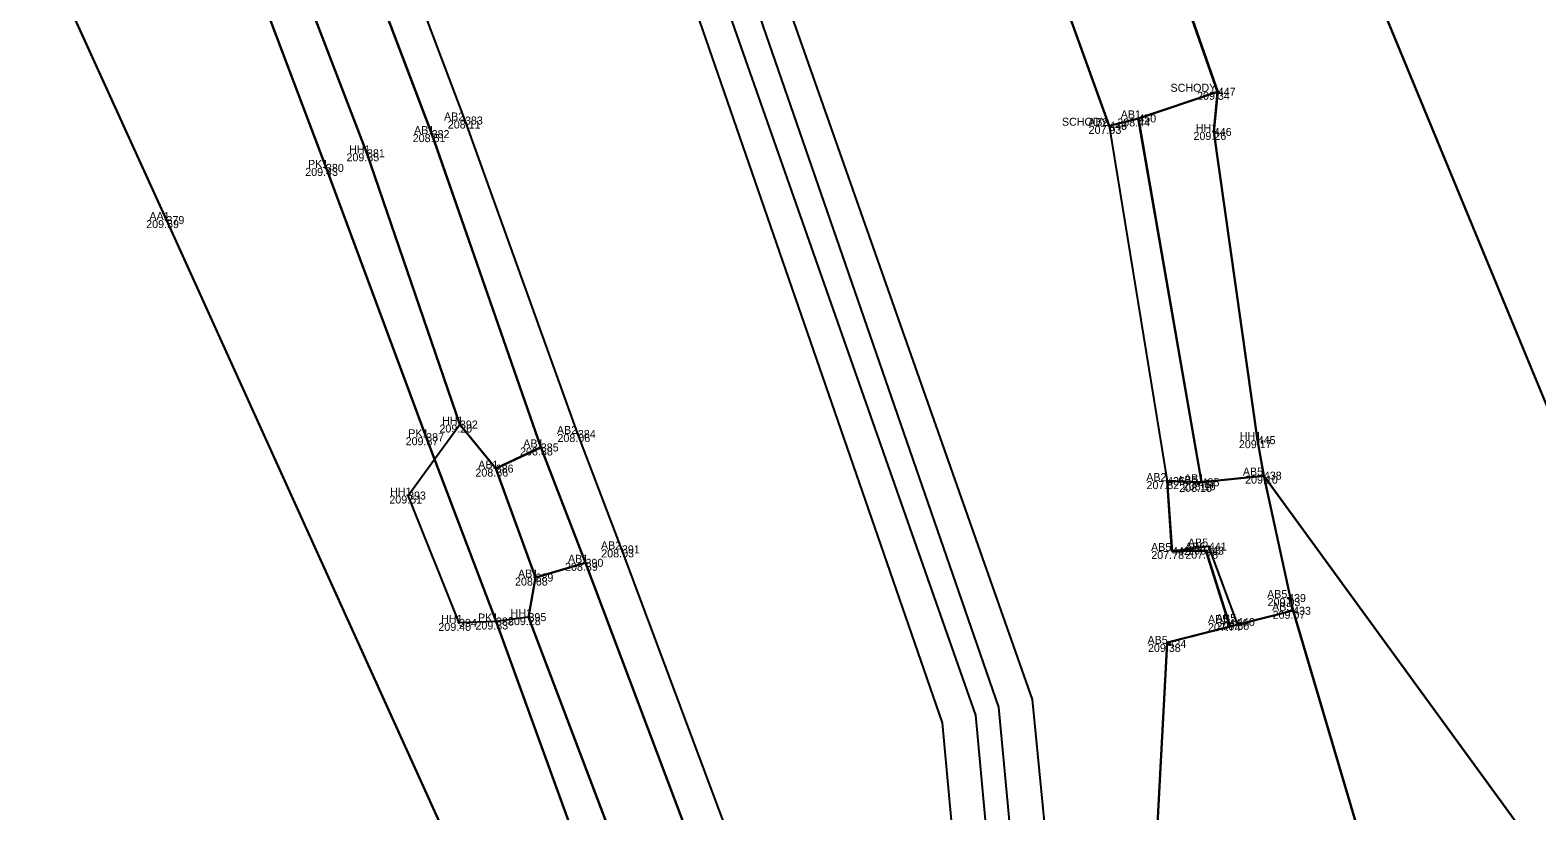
# Model space of a CAD drawing. Extents: x -263091 to -262565, y -1238731 to -1237092.
# Drawn here: x -262849.37 to -262811.71, y -1238683.21 to -1238663.71 of the extents above; entities that cross this region are included whole.
import ezdxf

# ---------------------------------------------------------------- set-up
doc = ezdxf.new("R2010")
doc.units = 0
for name, color, linetype in [('01_Hrana_betónu', 7, 'Continuous'), ('02_Oplotenie', 7, 'Continuous'), ('03_Asfalt', 7, 'Continuous'), ('05_Hrana_terénu', 7, 'Continuous'), ('06_Schody', 7, 'Continuous'), ('07_Iné', 7, 'Continuous'), ('08_Mimo_zelene', 7, 'Continuous'), ('Groma (21)', 7, 'Continuous'), ('Groma (22)', 7, 'Continuous'), ('Groma (23)', 7, 'Continuous'), ('Groma (24)', 7, 'Continuous'), ('U001_Betónové_panely_oblast', 7, 'Continuous'), ('U001_Betóny_prídavné', 7, 'Continuous'), ('U001_Ostatné_plochy', 7, 'Continuous'), ('U001_Schody', 7, 'Continuous'), ('U001_Zeleň_mimo', 7, 'Continuous'), ('U001_Zeleň_vnútro', 7, 'Continuous'), ('U001_Zeleň_zatrávňovač', 7, 'Continuous')]:
    doc.layers.add(name, color=color, linetype=linetype)

msp = doc.modelspace()

# ---------------------------------------------------------------- linework, layer by layer
at = {"layer": '01_Hrana_betónu'}
for p, q in [((-262822.4, -1238666.098), (-262820.949, -1238674.974)), ((-262820.09, -1238675.003), (-262821.671, -1238665.912))]:
    msp.add_line(p, q, dxfattribs=at)
for points in [[(-262945.09, -1238415.05), (-262943.108, -1238420.999), (-262942.065, -1238424.139), (-262934.754, -1238438.855), (-262923.683, -1238461.06), (-262913.753, -1238481.232), (-262903.896, -1238501.06), (-262894.759, -1238519.856), (-262890.317, -1238530.551), (-262883.158, -1238545.169), (-262873.572, -1238564.111), (-262869.728, -1238571.951), (-262860.562, -1238590.864), (-262854.835, -1238604.812), (-262840.38, -1238642.586), (-262833.174, -1238661.935), (-262826.575, -1238681.018), (-262825.738, -1238690.053), (-262824.527, -1238692.082)], [(-262821.464, -1238691.979), (-262823.978, -1238691.385), (-262824.893, -1238689.953), (-262825.729, -1238680.825), (-262832.468, -1238661.625), (-262839.672, -1238642.452), (-262854.271, -1238604.655), (-262859.863, -1238590.55), (-262868.949, -1238571.69), (-262872.864, -1238563.867), (-262882.403, -1238544.934), (-262889.591, -1238530.296), (-262894.035, -1238519.557), (-262903.102, -1238500.748), (-262912.912, -1238480.97), (-262922.987, -1238460.594), (-262933.962, -1238438.502), (-262941.314, -1238423.977), (-262942.296, -1238420.781), (-262943.962, -1238415.15)], [(-262941.142, -1238415.313), (-262941.461, -1238420.191), (-262940.383, -1238424.238), (-262933.343, -1238438.564), (-262922.27, -1238460.876), (-262912.449, -1238480.877), (-262902.557, -1238500.683), (-262893.416, -1238519.552), (-262889.058, -1238529.686), (-262881.962, -1238544.577), (-262872.106, -1238564.019), (-262868.478, -1238571.232), (-262859.211, -1238590.61), (-262852.998, -1238605.343), (-262846.933, -1238621.173), (-262838.559, -1238643.348), (-262831.894, -1238661.158), (-262825.164, -1238680.62), (-262824.312, -1238689.696), (-262823.847, -1238690.483), (-262822.763, -1238690.91), (-262821.486, -1238690.803)], [(-262821.555, -1238690.42), (-262822.731, -1238690.203), (-262823.426, -1238689.509), (-262824.318, -1238680.43), (-262831.163, -1238660.976), (-262837.946, -1238643.111), (-262846.365, -1238620.94), (-262852.333, -1238605.156), (-262858.618, -1238590.245), (-262867.784, -1238570.905), (-262871.416, -1238563.68), (-262881.223, -1238544.283), (-262888.392, -1238529.442), (-262892.626, -1238519.239), (-262901.725, -1238500.385), (-262911.6, -1238480.51), (-262921.479, -1238460.51), (-262932.607, -1238438.043), (-262939.752, -1238424.147), (-262940.771, -1238420.267), (-262940.559, -1238417.612), (-262940.205, -1238415.315)], [(-262821.612, -1238692.34), (-262824.527, -1238692.082), (-262827.229, -1238691.842), (-262828.578, -1238691.545), (-262829.254, -1238690.927), (-262834.577, -1238676.68), (-262835.677, -1238673.797), (-262838.498, -1238665.964), (-262846.729, -1238644.188), (-262854.634, -1238622.918), (-262863.262, -1238600.529), (-262868.088, -1238589.608)], [(-262868.934, -1238589.993), (-262864.101, -1238600.869), (-262855.602, -1238623.066), (-262847.622, -1238644.482), (-262839.332, -1238666.304), (-262836.604, -1238674.133), (-262835.486, -1238677.015), (-262830.144, -1238691.208), (-262829.282, -1238692.133), (-262827.58, -1238693.519), (-262820.969, -1238694.008)], [(-262820.949, -1238674.974), (-262820.828, -1238676.721), (-262819.978, -1238676.713), (-262819.376, -1238678.614), (-262820.948, -1238679.013), (-262821.555, -1238690.42)]]:
    msp.add_lwpolyline(points, dxfattribs=at)
at = {"layer": '02_Oplotenie'}
msp.add_lwpolyline([(-262896.033, -1238537.323), (-262884.611, -1238562.768), (-262875.332, -1238581.932), (-262871.26, -1238591.133), (-262867.507, -1238600.089), (-262859.113, -1238621.74), (-262850.323, -1238645.054), (-262841.974, -1238667.148), (-262839.469, -1238673.878), (-262839.26, -1238674.43), (-262837.725, -1238678.482), (-262834.801, -1238686.521), (-262833.14, -1238690.761), (-262828.35, -1238701.769), (-262822.156, -1238700.967), (-262816.462, -1238699.68), (-262807.77, -1238696.972), (-262807.339, -1238690.207)], dxfattribs=at)
at = {"layer": '03_Asfalt'}
for points in [[(-262804.465, -1238690.033), (-262818.631, -1238655.736), (-262826.695, -1238636.389), (-262836.855, -1238611.872), (-262842.406, -1238598.306), (-262850.452, -1238578.707), (-262858.82, -1238561.234), (-262870.509, -1238539), (-262873.344, -1238533.53), (-262876.375, -1238529.239), (-262880.031, -1238521.826), (-262869.115, -1238517.45), (-262870.175, -1238508.052), (-262871.319, -1238501.744), (-262886.895, -1238462.375), (-262895.067, -1238441.663), (-262905.824, -1238433.621), (-262917.716, -1238423.993), (-262928.896, -1238415.327), (-262941.774, -1238405.784), (-262954.673, -1238396.412), (-262962.054, -1238391.026)], [(-262881.2, -1238585.494), (-262874.644, -1238603.324), (-262866.886, -1238624.256), (-262857.388, -1238650.091), (-262854.721, -1238649.057), (-262851.25, -1238656.85), (-262845.959, -1238668.452), (-262837.314, -1238687.515), (-262834.926, -1238686.561), (-262833.211, -1238690.828), (-262828.426, -1238701.842), (-262822.233, -1238701.015), (-262822.159, -1238701.403), (-262816.354, -1238699.919), (-262807.207, -1238697.538)]]:
    msp.add_lwpolyline(points, dxfattribs=at)
at = {"layer": '05_Hrana_terénu'}
for points in [[(-262820.846, -1238694.953), (-262821.157, -1238695.132), (-262824.214, -1238695.234), (-262827.282, -1238694.67), (-262827.759, -1238694.543), (-262829.668, -1238693.915), (-262830.272, -1238693.55), (-262831.828, -1238691.771), (-262836.912, -1238678.373), (-262837.725, -1238678.482), (-262838.648, -1238678.516), (-262839.921, -1238675.334), (-262839.26, -1238674.43), (-262838.626, -1238673.561), (-262840.949, -1238666.783), (-262849.249, -1238645.167), (-262857.406, -1238624.309), (-262870.41, -1238590.811)], [(-262819.685, -1238665.246), (-262819.785, -1238666.25), (-262818.688, -1238673.951), (-262818.534, -1238674.837)]]:
    msp.add_lwpolyline(points, dxfattribs=at)
at = {"layer": '06_Schody'}
msp.add_lwpolyline([(-262825.01, -1238658.867), (-262824.362, -1238658.568), (-262822.278, -1238657.844), (-262819.685, -1238665.246), (-262821.671, -1238665.912), (-262822.4, -1238666.098)], close=True, dxfattribs=at)
at = {"layer": '07_Iné'}
for points in [[(-262835.486, -1238677.015), (-262836.736, -1238677.384), (-262837.731, -1238674.662), (-262836.604, -1238674.133)], [(-262820.828, -1238676.721), (-262820.949, -1238674.974), (-262820.09, -1238675.003), (-262818.534, -1238674.837), (-262817.803, -1238678.214), (-262819.181, -1238678.564), (-262819.908, -1238676.609), (-262820.828, -1238676.721), (-262819.978, -1238676.713), (-262819.376, -1238678.614)]]:
    msp.add_lwpolyline(points, dxfattribs=at)
at = {"layer": '08_Mimo_zelene'}
msp.add_lwpolyline([(-262817.803, -1238678.214), (-262819.181, -1238678.564), (-262819.376, -1238678.614), (-262820.948, -1238679.013), (-262821.555, -1238690.42), (-262821.486, -1238690.803), (-262821.464, -1238691.979), (-262821.612, -1238692.34), (-262819.863, -1238691.866), (-262819.273, -1238693.95), (-262818.147, -1238697.183), (-262812.645, -1238695.656), (-262813.715, -1238692.011)], close=True, dxfattribs=at)
at = {"layer": 'Groma (21)'}
for centre in [(-262819.685, -1238665.246), (-262838.498, -1238665.964), (-262822.4, -1238666.098), (-262822.399, -1238666.095), (-262821.671, -1238665.912), (-262839.332, -1238666.304), (-262819.785, -1238666.25), (-262840.949, -1238666.783), (-262841.974, -1238667.148), (-262845.959, -1238668.452), (-262838.626, -1238673.561), (-262839.469, -1238673.878), (-262835.677, -1238673.797), (-262818.688, -1238673.951), (-262836.604, -1238674.133), (-262837.731, -1238674.662), (-262818.534, -1238674.837), (-262820.949, -1238674.974), (-262820.175, -1238675.043), (-262820.09, -1238675.003), (-262839.921, -1238675.334), (-262834.577, -1238676.68), (-262820.828, -1238676.721), (-262819.978, -1238676.713), (-262819.908, -1238676.609), (-262835.486, -1238677.015), (-262836.736, -1238677.384), (-262817.928, -1238677.897), (-262817.803, -1238678.214), (-262838.648, -1238678.516), (-262837.725, -1238678.482), (-262836.912, -1238678.373), (-262819.406, -1238678.523), (-262819.206, -1238678.497), (-262820.917, -1238679.042)]:
    msp.add_circle(centre, 0.01, dxfattribs=at)
at = {"layer": 'U001_Betónové_panely_oblast'}
for points in [[(-262820.97, -1238694.01), (-262827.58, -1238693.52), (-262829.28, -1238692.13), (-262830.14, -1238691.21), (-262835.49, -1238677.02), (-262836.6, -1238674.13), (-262839.33, -1238666.3), (-262847.62, -1238644.48), (-262855.6, -1238623.07), (-262864.1, -1238600.87), (-262868.93, -1238589.99)], [(-262848.87, -1238596.84), (-262845.92, -1238603.87), (-262845.19, -1238603.53), (-262840.99, -1238614.59), (-262831.97, -1238638.45), (-262824.36, -1238658.57), (-262825.01, -1238658.87), (-262822.4, -1238666.1), (-262821.67, -1238665.91), (-262820.09, -1238675), (-262820.95, -1238674.97), (-262820.83, -1238676.72), (-262819.98, -1238676.71), (-262819.38, -1238678.61), (-262820.95, -1238679.01), (-262821.56, -1238690.42), (-262821.49, -1238690.8), (-262821.46, -1238691.98), (-262821.61, -1238692.34), (-262820.97, -1238694.01)], [(-262825.01, -1238658.87), (-262822.4, -1238666.1), (-262821.67, -1238665.91), (-262820.09, -1238675), (-262820.95, -1238674.97), (-262820.83, -1238676.72), (-262819.98, -1238676.71), (-262819.38, -1238678.61), (-262820.95, -1238679.01), (-262821.56, -1238690.42), (-262821.49, -1238690.8), (-262821.46, -1238691.98), (-262821.61, -1238692.34), (-262820.97, -1238694.01), (-262827.58, -1238693.52), (-262829.28, -1238692.13), (-262830.14, -1238691.21), (-262835.49, -1238677.02), (-262836.6, -1238674.13), (-262839.33, -1238666.3), (-262847.62, -1238644.48)]]:
    msp.add_lwpolyline(points, dxfattribs=at)
at = {"layer": 'U001_Betóny_prídavné'}
for points in [[(-262835.49, -1238677.02), (-262836.74, -1238677.38), (-262837.73, -1238674.66), (-262836.6, -1238674.13)], [(-262820.83, -1238676.72), (-262820.95, -1238674.97), (-262820.09, -1238675), (-262818.53, -1238674.84), (-262817.8, -1238678.21), (-262819.18, -1238678.56), (-262819.38, -1238678.61), (-262819.98, -1238676.71)]]:
    msp.add_lwpolyline(points, close=True, dxfattribs=at)
msp.add_lwpolyline([(-262819.38, -1238678.61), (-262819.98, -1238676.71), (-262820.83, -1238676.72), (-262820.95, -1238674.97), (-262820.09, -1238675), (-262818.53, -1238674.84), (-262817.8, -1238678.21), (-262819.18, -1238678.56), (-262819.38, -1238678.61)], dxfattribs=at)
at = {"layer": 'U001_Ostatné_plochy'}
msp.add_lwpolyline([(-262818.15, -1238697.18), (-262819.27, -1238693.95), (-262819.86, -1238691.87), (-262821.61, -1238692.34), (-262821.46, -1238691.98), (-262821.49, -1238690.8), (-262821.56, -1238690.42), (-262820.95, -1238679.01), (-262819.38, -1238678.61), (-262819.18, -1238678.56), (-262817.8, -1238678.21), (-262813.72, -1238692.01), (-262812.65, -1238695.66)], close=True, dxfattribs=at)
msp.add_lwpolyline([(-262818.15, -1238697.18), (-262819.27, -1238693.95), (-262819.86, -1238691.87), (-262821.61, -1238692.34), (-262821.46, -1238691.98), (-262821.49, -1238690.8), (-262821.56, -1238690.42), (-262820.95, -1238679.01), (-262819.38, -1238678.61), (-262819.18, -1238678.56), (-262817.8, -1238678.21), (-262813.72, -1238692.01), (-262812.65, -1238695.66), (-262818.15, -1238697.18)], dxfattribs=at)
at = {"layer": 'U001_Schody'}
msp.add_lwpolyline([(-262824.36, -1238658.57), (-262822.28, -1238657.84), (-262819.69, -1238665.25), (-262821.67, -1238665.91), (-262822.4, -1238666.1), (-262825.01, -1238658.87)], close=True, dxfattribs=at)
msp.add_lwpolyline([(-262822.4, -1238666.1), (-262825.01, -1238658.87), (-262824.36, -1238658.57), (-262822.28, -1238657.84), (-262819.69, -1238665.25), (-262821.67, -1238665.91), (-262822.4, -1238666.1)], dxfattribs=at)
at = {"layer": 'U001_Zeleň_mimo'}
for points in [[(-262962.05, -1238391.03), (-262954.67, -1238396.41), (-262941.77, -1238405.78), (-262928.9, -1238415.33), (-262917.72, -1238423.99), (-262905.82, -1238433.62), (-262895.07, -1238441.66), (-262886.9, -1238462.38), (-262871.32, -1238501.74), (-262870.18, -1238508.05), (-262869.12, -1238517.45), (-262880.03, -1238521.83), (-262876.38, -1238529.24), (-262873.34, -1238533.53), (-262870.51, -1238539), (-262858.82, -1238561.23), (-262850.45, -1238578.71), (-262842.41, -1238598.31), (-262836.86, -1238611.87), (-262826.7, -1238636.39), (-262818.63, -1238655.74), (-262804.47, -1238690.03)], [(-262807.21, -1238697.54), (-262816.35, -1238699.92), (-262822.16, -1238701.4), (-262822.23, -1238701.02), (-262828.43, -1238701.84), (-262833.21, -1238690.83), (-262834.93, -1238686.56), (-262837.31, -1238687.52), (-262845.96, -1238668.45), (-262851.25, -1238656.85), (-262854.72, -1238649.06), (-262857.39, -1238650.09), (-262866.89, -1238624.26), (-262874.64, -1238603.32), (-262881.2, -1238585.49)], [(-262871.26, -1238591.13), (-262867.51, -1238600.09), (-262859.11, -1238621.74), (-262850.32, -1238645.05), (-262841.97, -1238667.15), (-262839.47, -1238673.88), (-262839.26, -1238674.43), (-262837.72, -1238678.48), (-262834.8, -1238686.52), (-262833.14, -1238690.76), (-262828.35, -1238701.77), (-262822.16, -1238700.97), (-262816.46, -1238699.68), (-262807.77, -1238696.97)], [(-262807.34, -1238690.21), (-262818.53, -1238674.84), (-262818.69, -1238673.95), (-262819.78, -1238666.25), (-262819.69, -1238665.25), (-262822.28, -1238657.84), (-262830.39, -1238637.77), (-262839.6, -1238613.33), (-262842.24, -1238606.86), (-262843.24, -1238602.62), (-262846.18, -1238595.66)]]:
    msp.add_lwpolyline(points, dxfattribs=at)
at = {"layer": 'U001_Zeleň_vnútro'}
for points in [[(-262870.41, -1238590.81), (-262857.41, -1238624.31), (-262849.25, -1238645.17), (-262840.95, -1238666.78), (-262838.63, -1238673.56), (-262837.73, -1238674.66), (-262836.74, -1238677.38), (-262836.91, -1238678.37), (-262831.83, -1238691.77), (-262830.27, -1238693.55), (-262829.67, -1238693.92), (-262827.76, -1238694.54), (-262827.28, -1238694.67), (-262824.21, -1238695.23), (-262821.16, -1238695.13), (-262820.85, -1238694.95), (-262819.27, -1238693.95), (-262818.15, -1238697.18), (-262812.65, -1238695.66), (-262813.72, -1238692.01), (-262817.8, -1238678.21), (-262818.53, -1238674.84), (-262807.34, -1238690.21)], [(-262870.41, -1238590.81), (-262857.41, -1238624.31), (-262849.25, -1238645.17), (-262840.95, -1238666.78), (-262838.63, -1238673.56), (-262837.73, -1238674.66), (-262836.74, -1238677.38), (-262836.91, -1238678.37), (-262831.83, -1238691.77), (-262830.27, -1238693.55), (-262829.67, -1238693.92), (-262827.76, -1238694.54), (-262827.28, -1238694.67), (-262824.21, -1238695.23), (-262821.16, -1238695.13), (-262820.85, -1238694.95), (-262819.27, -1238693.95), (-262818.15, -1238697.18), (-262812.65, -1238695.66), (-262813.72, -1238692.01), (-262817.8, -1238678.21), (-262818.53, -1238674.84), (-262807.34, -1238690.21)], [(-262807.77, -1238696.97), (-262816.46, -1238699.68), (-262822.16, -1238700.97), (-262828.35, -1238701.77), (-262833.14, -1238690.76), (-262834.8, -1238686.52), (-262837.72, -1238678.48), (-262839.26, -1238674.43), (-262839.47, -1238673.88), (-262841.97, -1238667.15), (-262850.32, -1238645.05), (-262859.11, -1238621.74), (-262867.51, -1238600.09), (-262871.26, -1238591.13)], [(-262828.35, -1238701.77), (-262833.14, -1238690.76), (-262834.8, -1238686.52), (-262837.72, -1238678.48), (-262839.26, -1238674.43), (-262839.47, -1238673.88), (-262841.97, -1238667.15), (-262850.32, -1238645.05), (-262859.11, -1238621.74), (-262867.51, -1238600.09), (-262871.26, -1238591.13)]]:
    msp.add_lwpolyline(points, dxfattribs=at)
at = {"layer": 'U001_Zeleň_zatrávňovač'}
for points in [[(-262868.93, -1238589.99), (-262864.1, -1238600.87), (-262855.6, -1238623.07), (-262847.62, -1238644.48), (-262839.33, -1238666.3), (-262836.6, -1238674.13), (-262837.73, -1238674.66), (-262838.63, -1238673.56), (-262840.95, -1238666.78), (-262849.25, -1238645.17), (-262857.41, -1238624.31), (-262870.41, -1238590.81)], [(-262868.93, -1238589.99), (-262864.1, -1238600.87), (-262855.6, -1238623.07), (-262847.62, -1238644.48), (-262839.33, -1238666.3), (-262836.6, -1238674.13), (-262837.73, -1238674.66)], [(-262837.73, -1238674.66), (-262838.63, -1238673.56), (-262840.95, -1238666.78), (-262849.25, -1238645.17), (-262857.41, -1238624.31), (-262870.41, -1238590.81)], [(-262820.09, -1238675), (-262821.67, -1238665.91), (-262819.69, -1238665.25), (-262819.78, -1238666.25), (-262818.69, -1238673.95), (-262818.53, -1238674.84), (-262820.09, -1238675)], [(-262824.21, -1238695.23), (-262827.28, -1238694.67), (-262827.76, -1238694.54), (-262829.67, -1238693.92), (-262830.27, -1238693.55), (-262831.83, -1238691.77), (-262836.91, -1238678.37), (-262836.74, -1238677.38), (-262835.49, -1238677.02), (-262830.14, -1238691.21), (-262829.28, -1238692.13), (-262827.58, -1238693.52), (-262820.97, -1238694.01), (-262820.85, -1238694.95), (-262821.16, -1238695.13), (-262824.21, -1238695.23)]]:
    msp.add_lwpolyline(points, dxfattribs=at)
for points in [[(-262819.78, -1238666.25), (-262818.69, -1238673.95), (-262818.53, -1238674.84), (-262820.09, -1238675), (-262821.67, -1238665.91), (-262819.69, -1238665.25)], [(-262836.91, -1238678.37), (-262836.74, -1238677.38), (-262835.49, -1238677.02), (-262830.14, -1238691.21), (-262829.28, -1238692.13), (-262827.58, -1238693.52), (-262820.97, -1238694.01), (-262820.85, -1238694.95), (-262821.16, -1238695.13), (-262824.21, -1238695.23), (-262827.28, -1238694.67), (-262827.76, -1238694.54), (-262829.67, -1238693.92), (-262830.27, -1238693.55), (-262831.83, -1238691.77)]]:
    msp.add_lwpolyline(points, close=True, dxfattribs=at)

# ---------------------------------------------------------------- texts
at = {"layer": 'Groma (22)'}
for s, p in [('447', (-262819.685, -1238665.346)), ('383', (-262838.498, -1238666.064)), ('449', (-262822.4, -1238666.198)), ('448', (-262822.399, -1238666.195)), ('450', (-262821.671, -1238666.012)), ('446', (-262819.785, -1238666.35)), ('382', (-262839.332, -1238666.404)), ('381', (-262840.949, -1238666.883)), ('380', (-262841.974, -1238667.248)), ('379', (-262845.959, -1238668.552)), ('392', (-262838.626, -1238673.661)), ('384', (-262835.677, -1238673.897)), ('387', (-262839.469, -1238673.978)), ('385', (-262836.604, -1238674.233)), ('445', (-262818.688, -1238674.051)), ('386', (-262837.731, -1238674.762)), ('438', (-262818.534, -1238674.937)), ('436', (-262820.949, -1238675.074)), ('437', (-262820.175, -1238675.143)), ('435', (-262820.09, -1238675.103)), ('393', (-262839.921, -1238675.434)), ('391', (-262834.577, -1238676.78)), ('442', (-262820.828, -1238676.821)), ('443', (-262819.978, -1238676.813)), ('441', (-262819.908, -1238676.709)), ('390', (-262835.486, -1238677.115)), ('389', (-262836.736, -1238677.484)), ('439', (-262817.928, -1238677.997)), ('433', (-262817.803, -1238678.314)), ('394', (-262838.648, -1238678.616)), ('388', (-262837.725, -1238678.582)), ('395', (-262836.912, -1238678.473)), ('444', (-262819.406, -1238678.623)), ('440', (-262819.206, -1238678.597)), ('434', (-262820.917, -1238679.142))]:
    msp.add_text(s, height=0.2, dxfattribs=at).set_placement(p)
at = {"layer": 'Groma (23)'}
for s, p in [('209.34', (-262820.202, -1238665.446)), ('208.11', (-262838.928, -1238666.164)), ('207.93', (-262822.913, -1238666.298)), ('207.93', (-262822.912, -1238666.295)), ('208.44', (-262822.197, -1238666.112)), ('208.51', (-262839.805, -1238666.504)), ('209.26', (-262820.292, -1238666.45)), ('209.35', (-262841.461, -1238666.983)), ('209.43', (-262842.491, -1238667.348)), ('209.59', (-262846.466, -1238668.652)), ('209.20', (-262839.137, -1238673.761)), ('209.37', (-262839.982, -1238674.078)), ('208.06', (-262836.188, -1238673.997)), ('209.17', (-262819.157, -1238674.151)), ('208.38', (-262837.121, -1238674.333)), ('208.66', (-262838.238, -1238674.862)), ('207.82', (-262821.466, -1238675.174)), ('208.18', (-262820.648, -1238675.243)), ('208.16', (-262820.558, -1238675.203)), ('209.10', (-262819.002, -1238675.037)), ('209.51', (-262840.389, -1238675.534)), ('208.03', (-262835.093, -1238676.88)), ('207.78', (-262820.496, -1238676.913)), ('208.58', (-262820.425, -1238676.809)), ('208.39', (-262835.998, -1238677.215)), ('207.78', (-262821.346, -1238676.921)), ('208.68', (-262837.248, -1238677.584)), ('209.03', (-262818.439, -1238678.097)), ('209.07', (-262818.315, -1238678.414)), ('209.40', (-262839.164, -1238678.716)), ('209.33', (-262838.237, -1238678.682)), ('209.28', (-262837.424, -1238678.573)), ('207.74', (-262819.929, -1238678.723)), ('208.60', (-262819.717, -1238678.697)), ('209.38', (-262821.429, -1238679.242))]:
    msp.add_text(s, height=0.2, dxfattribs=at).set_placement(p)
at = {"layer": 'Groma (24)'}
for s, p in [('SCHODY', (-262820.866, -1238665.246)), ('AB2', (-262839.022, -1238665.964)), ('AB1', (-262822.109, -1238665.912)), ('AB1', (-262839.77, -1238666.304)), ('SCHODY', (-262823.58, -1238666.095)), ('AB2', (-262822.924, -1238666.098)), ('HH1', (-262820.232, -1238666.25)), ('HH1', (-262841.396, -1238666.783)), ('PK1', (-262842.421, -1238667.148)), ('AA1', (-262846.387, -1238668.452)), ('PK1', (-262839.916, -1238673.878)), ('HH1', (-262839.073, -1238673.561)), ('AB2', (-262836.201, -1238673.797)), ('AB1', (-262837.042, -1238674.133)), ('HH1', (-262819.135, -1238673.951)), ('AB1', (-262838.169, -1238674.662)), ('AB2', (-262821.473, -1238674.974)), ('AB1', (-262820.528, -1238675.003)), ('AB5', (-262819.058, -1238674.837)), ('HH1', (-262840.368, -1238675.334)), ('AB5', (-262820.699, -1238675.043)), ('AB2', (-262835.101, -1238676.68)), ('AB5', (-262821.352, -1238676.721)), ('AB5', (-262820.502, -1238676.713)), ('AB5', (-262820.432, -1238676.609)), ('AB1', (-262835.924, -1238677.015)), ('AB1', (-262837.174, -1238677.384)), ('AB5', (-262818.452, -1238677.897)), ('HH1', (-262837.359, -1238678.373)), ('AB5', (-262818.327, -1238678.214)), ('HH1', (-262839.095, -1238678.516)), ('PK1', (-262838.172, -1238678.482)), ('AB5', (-262819.93, -1238678.523)), ('AB5', (-262819.73, -1238678.497)), ('AB5', (-262821.441, -1238679.042))]:
    msp.add_text(s, height=0.2, dxfattribs=at).set_placement(p)

doc.saveas('drawing.dxf')
